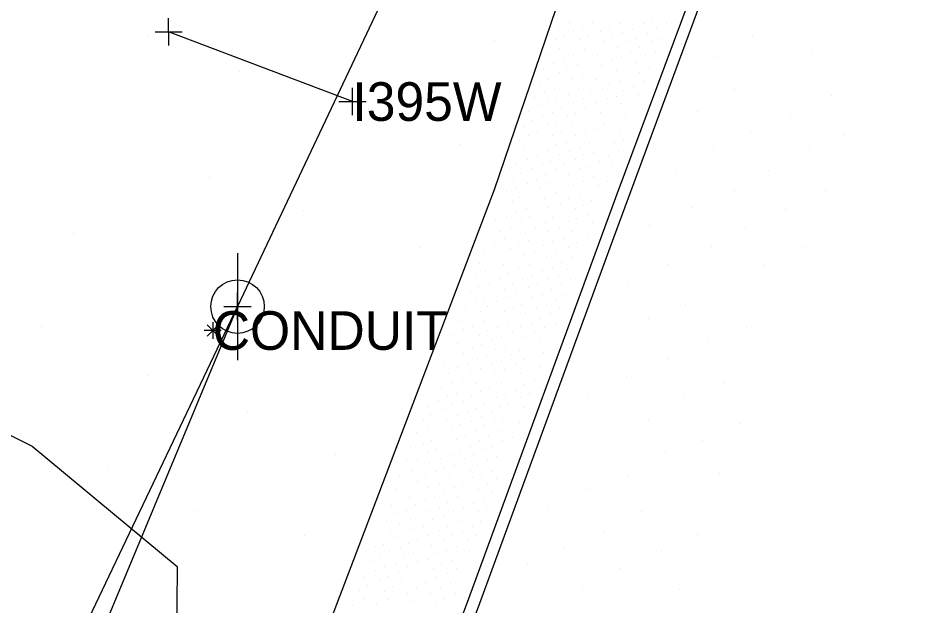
# Model space of a CAD drawing. Extents: x 1729983 to 1730242, y 468641 to 469019.
# Drawn here: x 1730086.95 to 1730129, y 468940.46 to 468967.85 of the extents above; entities that cross this region are included whole.
import ezdxf

# ---------------------------------------------------------------- set-up
doc = ezdxf.new("R2010")
doc.units = 0
for name, color, linetype in [('Default', 7, 'Continuous'), ('S_Curb_Type_1', 7, 'Continuous'), ('S_Ground_SpotElevation', 7, 'Continuous'), ('S_Misc_MiscItems', 7, 'Continuous'), ('S_Roadway_Edge_Pavement', 7, 'Continuous'), ('S_Roadway_Sidewalks', 7, 'Continuous'), ('S_Survey_Shot', 7, 'Continuous'), ('S_Text', 7, 'Continuous'), ('S_Traffic_Sign_DoublePost', 7, 'Continuous'), ('S_Trees_Bush_Line', 7, 'Continuous'), ('S_Utilities_AG_Communications', 7, 'Continuous'), ('S_Utilities_GuyWire3', 7, 'Continuous'), ('S_Utilities_Pole_Power', 7, 'Continuous')]:
    doc.layers.add(name, color=color, linetype=linetype)

# ---------------------------------------------------------------- blocks, each defined once
blk = doc.blocks.new('POINT_DISPLAY')
at = {"layer": 'Default'}
blk.add_line((0, 0), (0, 0), dxfattribs=at)

msp = doc.modelspace()

# ---------------------------------------------------------------- linework, layer by layer
at = {"layer": 'S_Curb_Type_1'}
msp.add_lwpolyline([(1730127.344, 469003.745), (1730128.313, 469003.209), (1730129.005, 469001.957), (1730128.001, 468995.343), (1730121.966, 468978.7), (1730114.875, 468959.641), (1730107.952, 468940.794), (1730100.667, 468921.305), (1730089.464, 468890.124), (1730080.18, 468865.229), (1730072.814, 468845.368), (1730066.167, 468827.336), (1730059.271, 468808.011), (1730050.413, 468784.194), (1730032.961, 468736.85), (1730026.597, 468719.521), (1730017.926, 468696.116)], dxfattribs=at)
at = {"layer": 'S_Misc_MiscItems'}
for p, q in [((1730096.026, 468953.685), (1730096.026, 468952.899)), ((1730096.419, 468953.292), (1730095.633, 468953.292)), ((1730096.288, 468953.03), (1730095.764, 468953.554)), ((1730096.288, 468953.554), (1730095.764, 468953.03))]:
    msp.add_line(p, q, dxfattribs=at)
at = {"layer": 'S_Roadway_Edge_Pavement'}
msp.add_lwpolyline([(1730128.624, 468995.344), (1730122.317, 468978.183), (1730114.717, 468957.613), (1730108.465, 468940.563), (1730101.987, 468923.258), (1730100.18, 468918.245), (1730089.85, 468889.621), (1730080.624, 468864.761), (1730073.33, 468845.31), (1730066.507, 468826.616), (1730059.612, 468807.458), (1730050.88, 468783.514), (1730042.113, 468759.912), (1730034.557, 468739.828), (1730031.891, 468732.687), (1730026.743, 468718.512), (1730018.434, 468695.905)], dxfattribs=at)
at = {"layer": 'S_Roadway_Sidewalks'}
msp.add_lwpolyline([(1730119.084, 469000.57), (1730119.448, 468999.332), (1730120.056, 468996.986), (1730120.498, 468995.123), (1730119.297, 468990.738), (1730114.901, 468976.742), (1730109.15, 468959.847), (1730103.637, 468945.339), (1730096.174, 468925.752), (1730091.001, 468911.699), (1730089.34, 468910.169), (1730081.674, 468911.604)], dxfattribs=at)
at = {"layer": 'S_Survey_Shot'}
for p, q in [((1730093.972, 468966.579), (1730093.97, 468967.851)), ((1730093.335, 468967.214), (1730094.607, 468967.216)), ((1730093.971, 468967.215), (1730093.971, 468967.215)), ((1730102.539, 468963.327), (1730102.537, 468964.599)), ((1730101.902, 468963.962), (1730103.174, 468963.964)), ((1730102.538, 468963.963), (1730102.538, 468963.963)), ((1730097.185, 468953.772), (1730097.183, 468955.044)), ((1730096.548, 468954.407), (1730097.82, 468954.409)), ((1730097.184, 468954.408), (1730097.184, 468954.408))]:
    msp.add_line(p, q, dxfattribs=at)
at = {"layer": 'S_Traffic_Sign_DoublePost'}
msp.add_lwpolyline([(1730102.538, 468963.963), (1730093.971, 468967.215)], dxfattribs=at)
at = {"layer": 'S_Trees_Bush_Line'}
msp.add_lwpolyline([(1730059.491, 468966.653), (1730069.864, 468958.481), (1730078.631, 468952.373), (1730087.606, 468947.904), (1730094.366, 468942.3), (1730094.314, 468936.887), (1730092.999, 468931.526), (1730087.455, 468921.933), (1730084.021, 468916.346), (1730080.816, 468914.539)], dxfattribs=at)
at = {"layer": 'S_Utilities_AG_Communications'}
msp.add_lwpolyline([(1730120.945, 469004.632), (1730097.184, 468954.408), (1730085.556, 468926.546), (1730082.304, 468910.964), (1730034.658, 468781.323), (1729998.254, 468703.261)], dxfattribs=at)
at = {"layer": 'S_Utilities_GuyWire3'}
msp.add_lwpolyline([(1730083.167, 468925.031), (1730097.184, 468954.408)], dxfattribs=at)
at = {"layer": 'S_Utilities_Pole_Power'}
msp.add_line((1730097.184, 468956.903), (1730097.184, 468951.913), dxfattribs=at)
msp.add_circle((1730097.184, 468954.408), 1.248, dxfattribs=at)

# ---------------------------------------------------------------- block references
at = {"layer": 'S_Ground_SpotElevation'}
for p in [(1730112.671, 468967.651), (1730113.731, 468967.651), (1730114.979, 468967.608), (1730116.102, 468967.587), (1730116.504, 468967.815), (1730117.176, 468967.62), (1730123.145, 468967.8), (1730112.165, 468967.479), (1730112.848, 468967.215), (1730113.272, 468967.451), (1730114.087, 468967.229), (1730114.518, 468967.447), (1730115.144, 468967.188), (1730115.597, 468967.321), (1730116.314, 468967.14), (1730116.72, 468967.362), (1730092.985, 468966.99), (1730109.179, 468966.788), (1730112.033, 468966.84), (1730112.378, 468967.063), (1730113.134, 468966.85), (1730113.558, 468966.992), (1730114.253, 468966.759), (1730114.69, 468966.947), (1730115.318, 468966.753), (1730115.772, 468966.908), (1730116.488, 468966.744), (1730116.937, 468966.901), (1730121.186, 468966.972), (1730125.914, 468966.975), (1730112.18, 468966.416), (1730112.71, 468966.573), (1730113.384, 468966.371), (1730114.916, 468966.498), (1730115.505, 468966.309), (1730115.943, 468966.482), (1730116.692, 468966.282), (1730111.741, 468966.178), (1730112.373, 468965.969), (1730112.87, 468966.121), (1730113.476, 468965.873), (1730113.957, 468966.126), (1730114.607, 468965.892), (1730115.086, 468966.064), (1730116.225, 468966.087), (1730119.421, 468966.021), (1730124.012, 468966.211), (1730111.473, 468965.457), (1730111.894, 468965.715), (1730112.542, 468965.472), (1730113.034, 468965.686), (1730114.169, 468965.641), (1730114.864, 468965.433), (1730115.311, 468965.62), (1730115.781, 468965.776), (1730116.371, 468965.531), (1730097.28, 468965.347), (1730112.174, 468965.318), (1730112.79, 468965.057), (1730113.277, 468965.238), (1730114.341, 468965.177), (1730115.472, 468965.133), (1730115.946, 468965.338), (1730122.02, 468965.23), (1730111.282, 468964.829), (1730111.662, 468964.999), (1730111.981, 468964.591), (1730112.339, 468964.742), (1730113.098, 468964.592), (1730113.471, 468964.772), (1730113.907, 468964.976), (1730114.536, 468964.743), (1730115.046, 468964.878), (1730115.666, 468964.662), (1730116.114, 468964.877), (1730111.023, 468964.173), (1730111.501, 468964.406), (1730112.61, 468964.315), (1730113.654, 468964.345), (1730114.196, 468964.579), (1730114.831, 468964.207), (1730115.191, 468964.476), (1730115.902, 468964.292), (1730120.356, 468964.508), (1730124.885, 468964.263), (1730111.211, 468963.767), (1730111.623, 468963.985), (1730112.072, 468964.109), (1730112.855, 468963.87), (1730113.296, 468964.086), (1730113.88, 468963.919), (1730114.414, 468964.118), (1730115.033, 468963.868), (1730115.483, 468964.045), (1730102.513, 468963.43), (1730110.747, 468963.511), (1730111.413, 468963.33), (1730111.856, 468963.453), (1730112.28, 468963.707), (1730112.919, 468963.421), (1730113.429, 468963.68), (1730114.108, 468963.45), (1730114.576, 468963.612), (1730115.259, 468963.347), (1730115.716, 468963.589), (1730118.635, 468963.505), (1730122.969, 468963.339), (1730110.897, 468963.078), (1730112.05, 468963.006), (1730112.546, 468963.293), (1730113.231, 468962.94), (1730113.602, 468963.228), (1730114.29, 468962.96), (1730114.709, 468963.198), (1730110.539, 468962.817), (1730111.15, 468962.564), (1730111.624, 468962.874), (1730112.293, 468962.505), (1730112.749, 468962.828), (1730113.817, 468962.682), (1730114.587, 468962.491), (1730114.976, 468962.634), (1730121.09, 468962.524), (1730110.318, 468962.171), (1730110.766, 468962.365), (1730111.36, 468962.177), (1730111.868, 468962.368), (1730112.937, 468962.385), (1730113.423, 468962.475), (1730115.185, 468962.17), (1730125.508, 468962.447), (1730107.534, 468961.951), (1730110.533, 468961.743), (1730111.614, 468961.684), (1730112.061, 468961.972), (1730112.526, 468962.055), (1730112.676, 468961.649), (1730113.166, 468961.83), (1730113.611, 468962.025), (1730114.331, 468961.859), (1730114.764, 468962.049), (1730114.953, 468961.654), (1730119.386, 468961.872), (1730123.85, 468961.729), (1730110.711, 468961.253), (1730111.168, 468961.434), (1730112.21, 468961.507), (1730112.965, 468961.245), (1730113.329, 468961.477), (1730113.785, 468961.599), (1730114.496, 468961.457), (1730109.851, 468960.844), (1730110.202, 468961.009), (1730110.92, 468960.824), (1730111.406, 468961.049), (1730111.754, 468961.186), (1730112.441, 468961.037), (1730113.168, 468960.822), (1730113.579, 468960.948), (1730114.065, 468961.157), (1730114.636, 468960.968), (1730095.858, 468960.403), (1730110.378, 468960.597), (1730111.549, 468960.552), (1730112.037, 468960.801), (1730112.637, 468960.572), (1730113.775, 468960.477), (1730114.22, 468960.659), (1730117.59, 468960.753), (1730121.962, 468960.741), (1730110.036, 468960.357), (1730110.712, 468960.144), (1730111.101, 468960.353), (1730111.74, 468960.197), (1730112.848, 468960.113), (1730113.331, 468960.227), (1730114.008, 468960.062), (1730114.436, 468960.24), (1730109.718, 468959.773), (1730110.161, 468959.953), (1730110.847, 468959.654), (1730111.296, 468959.956), (1730111.993, 468959.741), (1730112.454, 468959.879), (1730113.144, 468959.618), (1730113.614, 468959.866), (1730114.191, 468959.622), (1730120.354, 468959.83), (1730124.58, 468959.817), (1730109.495, 468959.152), (1730109.992, 468959.31), (1730110.326, 468959.5), (1730110.993, 468959.262), (1730111.481, 468959.455), (1730112.239, 468959.229), (1730112.633, 468959.464), (1730113.299, 468959.141), (1730113.708, 468959.329), (1730100.236, 468958.896), (1730110.187, 468958.788), (1730110.667, 468958.997), (1730111.687, 468959.017), (1730112.923, 468958.972), (1730118.406, 468959.044), (1730122.713, 468958.915), (1730109.229, 468958.445), (1730109.713, 468958.607), (1730110.408, 468958.386), (1730110.813, 468958.6), (1730111.555, 468958.314), (1730111.89, 468958.574), (1730112.598, 468958.37), (1730112.987, 468958.518), (1730113.499, 468958.686), (1730113.733, 468958.34), (1730109.445, 468957.928), (1730109.904, 468958.096), (1730110.62, 468957.868), (1730111.077, 468958.104), (1730111.679, 468957.884), (1730112.181, 468958.089), (1730112.761, 468957.909), (1730113.236, 468958.047), (1730116.391, 468958.193), (1730120.886, 468958.038), (1730089.516, 468957.81), (1730108.971, 468957.764), (1730109.639, 468957.58), (1730110.11, 468957.757), (1730110.737, 468957.508), (1730111.216, 468957.689), (1730112.399, 468957.598), (1730113.491, 468957.648), (1730105.658, 468957.142), (1730108.711, 468957.044), (1730109.148, 468957.27), (1730109.898, 468957.111), (1730110.269, 468957.257), (1730111.443, 468957.257), (1730111.888, 468957.436), (1730112.041, 468957.023), (1730112.602, 468957.167), (1730112.986, 468957.399), (1730119.288, 468957.22), (1730123.546, 468957.194), (1730108.985, 468956.626), (1730109.371, 468956.891), (1730110.091, 468956.613), (1730110.546, 468956.837), (1730111.026, 468956.966), (1730111.605, 468956.73), (1730112.737, 468956.697), (1730113.229, 468956.905), (1730108.488, 468956.408), (1730109.108, 468956.226), (1730109.577, 468956.37), (1730110.271, 468956.193), (1730110.796, 468956.365), (1730111.2, 468956.555), (1730111.861, 468956.25), (1730112.282, 468956.468), (1730117.288, 468956.371), (1730121.762, 468956.331), (1730108.329, 468955.777), (1730108.742, 468956.024), (1730109.801, 468955.947), (1730110.934, 468955.834), (1730111.416, 468956.107), (1730112.136, 468955.856), (1730112.553, 468956.147), (1730108.406, 468955.347), (1730108.933, 468955.456), (1730109.399, 468955.696), (1730110.024, 468955.457), (1730110.477, 468955.653), (1730111.156, 468955.441), (1730111.622, 468955.703), (1730112.289, 468955.426), (1730112.725, 468955.648), (1730115.421, 468955.508), (1730120.185, 468955.404), (1730108.05, 468955.111), (1730109.612, 468955.217), (1730110.208, 468955.04), (1730110.756, 468955.301), (1730111.382, 468954.974), (1730111.822, 468955.205), (1730112.476, 468954.966), (1730108.273, 468954.651), (1730108.659, 468954.804), (1730109.268, 468954.631), (1730109.848, 468954.811), (1730110.424, 468954.51), (1730110.892, 468954.839), (1730112.05, 468954.7), (1730098.78, 468954.358), (1730107.811, 468954.434), (1730108.491, 468954.171), (1730108.822, 468954.429), (1730109.615, 468954.191), (1730110.04, 468954.354), (1730110.62, 468954.143), (1730111.12, 468954.366), (1730111.604, 468954.486), (1730111.777, 468954.102), (1730112.201, 468954.356), (1730118.086, 468954.493), (1730122.538, 468954.406), (1730107.484, 468953.727), (1730108.696, 468953.702), (1730109.1, 468953.994), (1730109.76, 468953.666), (1730110.253, 468953.928), (1730111.286, 468953.868), (1730116.331, 468953.833), (1730088.062, 468953.484), (1730107.741, 468953.318), (1730108.144, 468953.474), (1730108.853, 468953.3), (1730109.323, 468953.421), (1730110.011, 468953.259), (1730110.395, 468953.457), (1730110.897, 468953.61), (1730111.485, 468953.455), (1730111.999, 468953.604), (1730120.927, 468953.414), (1730103.7, 468952.859), (1730107.253, 468953.122), (1730108.018, 468952.86), (1730108.477, 468953.081), (1730109.042, 468952.852), (1730109.496, 468952.996), (1730110.616, 468952.98), (1730111.019, 468953.186), (1730107.104, 468952.452), (1730107.435, 468952.697), (1730108.148, 468952.474), (1730108.543, 468952.636), (1730109.212, 468952.416), (1730109.696, 468952.542), (1730110.238, 468952.792), (1730110.829, 468952.513), (1730111.268, 468952.77), (1730114.595, 468952.8), (1730119.084, 468952.783), (1730107.26, 468952.019), (1730107.742, 468952.209), (1730108.803, 468952.129), (1730109.964, 468952.168), (1730110.35, 468952.34), (1730110.996, 468952.109), (1730111.468, 468952.247), (1730117.242, 468951.993), (1730106.827, 468951.785), (1730107.423, 468951.572), (1730107.909, 468951.768), (1730108.355, 468951.926), (1730109.016, 468951.714), (1730109.495, 468951.908), (1730110.126, 468951.741), (1730110.528, 468951.922), (1730111.26, 468951.624), (1730121.668, 468951.793), (1730092.97, 468951.192), (1730107.032, 468951.267), (1730108.069, 468951.276), (1730108.512, 468951.525), (1730109.176, 468951.283), (1730109.624, 468951.497), (1730110.398, 468951.289), (1730110.851, 468951.437), (1730115.341, 468951.139), (1730107.14, 468950.888), (1730107.668, 468951.053), (1730108.309, 468950.811), (1730108.762, 468951.035), (1730109.475, 468950.828), (1730109.868, 468950.964), (1730110.511, 468950.788), (1730111.022, 468950.97), (1730119.847, 468950.864), (1730106.688, 468950.652), (1730107.394, 468950.351), (1730107.866, 468950.623), (1730108.516, 468950.466), (1730108.916, 468950.606), (1730109.656, 468950.304), (1730110.123, 468950.509), (1730110.818, 468950.343), (1730113.571, 468950.295), (1730106.538, 468950.023), (1730106.976, 468950.277), (1730107.699, 468950.001), (1730108.076, 468950.254), (1730108.681, 468949.885), (1730109.274, 468950.166), (1730110.357, 468950.16), (1730117.991, 468950.165), (1730097.629, 468949.541), (1730106.024, 468949.747), (1730106.728, 468949.634), (1730107.192, 468949.838), (1730107.91, 468949.517), (1730108.329, 468949.667), (1730109.032, 468949.48), (1730109.441, 468949.75), (1730109.816, 468949.835), (1730110.098, 468949.492), (1730110.578, 468949.701), (1730105.834, 468949.085), (1730106.198, 468949.372), (1730106.938, 468949.105), (1730107.421, 468949.335), (1730108.115, 468949.039), (1730108.553, 468949.281), (1730109.159, 468949.035), (1730109.56, 468949.18), (1730116.35, 468949.157), (1730106.038, 468948.674), (1730107.158, 468948.678), (1730107.588, 468948.896), (1730108.313, 468948.654), (1730108.69, 468948.846), (1730109.331, 468948.633), (1730109.872, 468948.789), (1730110.328, 468948.986), (1730120.65, 468948.981), (1730105.551, 468948.519), (1730106.723, 468948.41), (1730107.37, 468948.211), (1730107.823, 468948.346), (1730108.872, 468948.34), (1730110.014, 468948.292), (1730114.364, 468948.395), (1730105.269, 468947.845), (1730105.832, 468948.041), (1730106.228, 468948.18), (1730106.898, 468948.001), (1730108.049, 468947.899), (1730108.453, 468948.169), (1730109.077, 468947.895), (1730109.529, 468948.149), (1730118.887, 468948.153), (1730101.733, 468947.507), (1730106.023, 468947.618), (1730106.468, 468947.744), (1730107.105, 468947.511), (1730107.6, 468947.687), (1730108.203, 468947.524), (1730108.606, 468947.741), (1730109.273, 468947.443), (1730109.737, 468947.648), (1730112.483, 468947.686), (1730117.155, 468947.638), (1730091.177, 468946.967), (1730105.039, 468947.213), (1730105.573, 468947.298), (1730106.112, 468947.093), (1730106.652, 468947.323), (1730107.281, 468947.02), (1730107.765, 468947.31), (1730108.355, 468947.044), (1730108.817, 468947.249), (1730105.314, 468946.765), (1730105.762, 468946.871), (1730106.406, 468946.702), (1730106.833, 468946.909), (1730107.482, 468946.573), (1730108.027, 468946.78), (1730108.564, 468946.599), (1730109.044, 468946.734), (1730115.422, 468946.526), (1730119.67, 468946.623), (1730104.756, 468946.483), (1730105, 468946.092), (1730105.559, 468946.251), (1730105.949, 468946.448), (1730106.59, 468946.138), (1730107.061, 468946.425), (1730107.693, 468946.217), (1730108.149, 468946.436), (1730108.838, 468946.139), (1730109.267, 468946.389), (1730104.609, 468945.863), (1730105.742, 468945.812), (1730106.108, 468945.996), (1730106.778, 468945.701), (1730107.302, 468945.979), (1730108.415, 468945.902), (1730109.082, 468945.731), (1730113.573, 468945.899), (1730118.082, 468945.764), (1730105.194, 468945.522), (1730105.933, 468945.36), (1730106.36, 468945.563), (1730106.96, 468945.278), (1730107.462, 468945.547), (1730108.632, 468945.479), (1730095.157, 468944.912), (1730104.361, 468945.156), (1730105.056, 468944.914), (1730105.496, 468945.183), (1730106.114, 468944.906), (1730106.58, 468945.066), (1730107.237, 468944.865), (1730107.717, 468945.024), (1730108.17, 468945.225), (1730108.403, 468944.86), (1730108.801, 468945.069), (1730111.622, 468945.068), (1730116.036, 468944.842), (1730104.132, 468944.43), (1730104.522, 468944.762), (1730105.23, 468944.462), (1730105.598, 468944.621), (1730106.28, 468944.48), (1730106.804, 468944.623), (1730107.872, 468944.632), (1730104.72, 468944.27), (1730105.396, 468944.014), (1730105.864, 468944.178), (1730106.952, 468944.172), (1730107.467, 468944.397), (1730108.123, 468944.145), (1730108.527, 468944.397), (1730100.283, 468943.738), (1730103.886, 468943.838), (1730104.298, 468943.976), (1730104.48, 468943.654), (1730104.888, 468943.817), (1730106.082, 468943.731), (1730106.589, 468943.966), (1730107.157, 468943.783), (1730107.652, 468943.89), (1730108.32, 468943.739), (1730114.265, 468943.919), (1730118.65, 468943.787), (1730103.628, 468943.235), (1730103.997, 468943.338), (1730104.766, 468943.182), (1730105.155, 468943.346), (1730105.579, 468943.547), (1730106.245, 468943.292), (1730106.779, 468943.549), (1730107.382, 468943.227), (1730107.929, 468943.497), (1730112.409, 468943.16), (1730104.272, 468942.995), (1730105.399, 468942.942), (1730105.757, 468943.079), (1730106.494, 468942.904), (1730106.906, 468943.022), (1730107.607, 468942.808), (1730108.015, 468942.996), (1730116.934, 468943.006), (1730103.389, 468942.505), (1730103.834, 468942.716), (1730104.534, 468942.443), (1730104.961, 468942.701), (1730105.58, 468942.51), (1730106.07, 468942.643), (1730106.715, 468942.439), (1730107.186, 468942.563), (1730110.692, 468942.389), (1730089.218, 468942.117), (1730103.599, 468942.107), (1730104.054, 468942.288), (1730104.676, 468942.037), (1730105.1, 468942.292), (1730105.775, 468942.02), (1730106.307, 468942.185), (1730106.955, 468941.953), (1730107.412, 468942.197), (1730115.063, 468942.2), (1730103.103, 468941.797), (1730103.797, 468941.651), (1730104.242, 468941.806), (1730104.84, 468941.605), (1730105.966, 468941.56), (1730106.445, 468941.763), (1730107.107, 468941.516), (1730102.891, 468941.184), (1730103.248, 468941.413), (1730104.027, 468941.143), (1730104.401, 468941.367), (1730105.107, 468941.056), (1730105.535, 468941.3), (1730106.628, 468941.257), (1730113.247, 468941.386), (1730117.798, 468941.203), (1730103.066, 468940.787), (1730103.53, 468941), (1730104.205, 468940.736), (1730104.646, 468940.908), (1730105.24, 468940.674), (1730105.764, 468940.921), (1730106.2, 468941.028), (1730106.441, 468940.617), (1730106.815, 468940.791), (1730107.329, 468941.015), (1730102.565, 468940.466), (1730103.67, 468940.503)]:
    msp.add_blockref('POINT_DISPLAY', p, dxfattribs=at)

# ---------------------------------------------------------------- texts
at = {"layer": 'S_Text'}
for s, p in [('I395W', (1730102.538, 468963.063)), ('CONDUIT', (1730096.026, 468952.392))]:
    msp.add_text(s, height=1.8, dxfattribs=at).set_placement(p)

doc.saveas('drawing.dxf')
